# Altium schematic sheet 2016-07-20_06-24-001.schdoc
size 267 x 118 mm; SheetNumber: 1; SheetTotal: 1
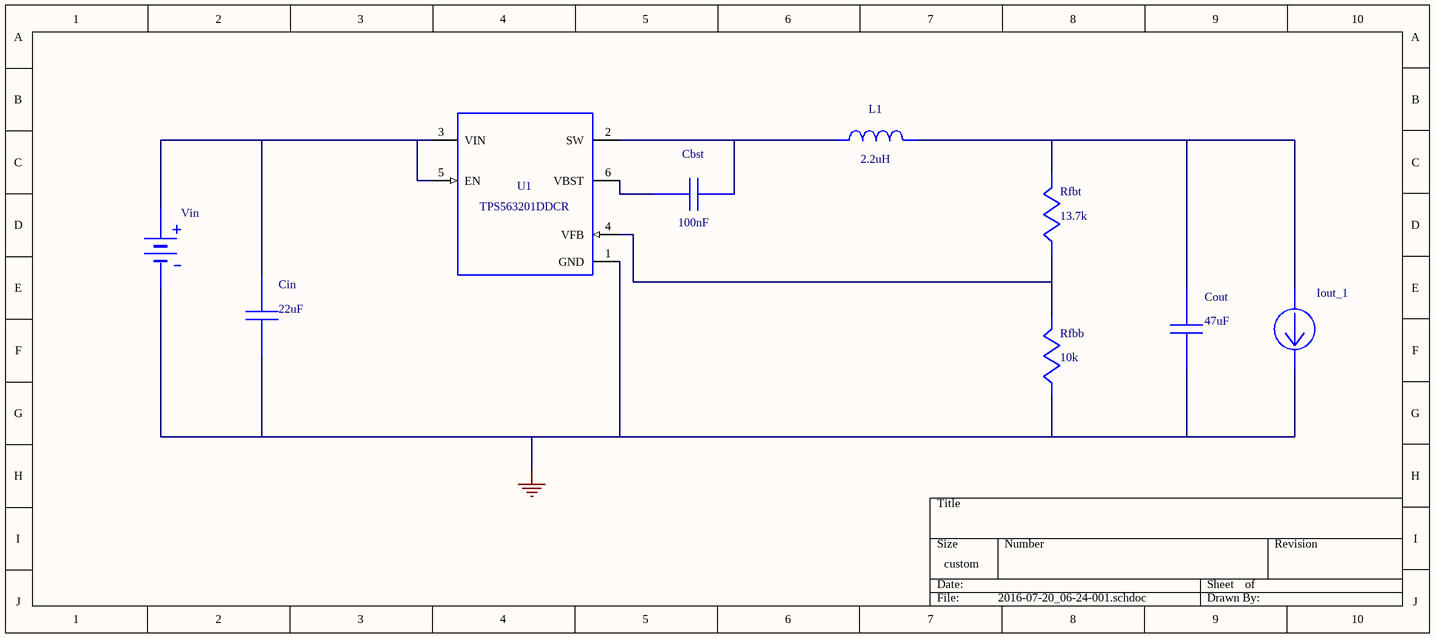
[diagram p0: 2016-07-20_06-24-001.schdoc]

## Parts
Cbst  value 100nF  (hidden comment: 08053C104KAT2A)
Cin  value 22uF  (hidden comment: GRM31CR61A226KE19L)
Cout  value 47uF  (hidden comment: C3216X5R1E476M160AC)
Iout_1  WB_CURRENT_LOAD  (value not drawn)
L1  value 2.2uH  (hidden comment: VLP8040T-2R2N)
Rfbb  value 10k  (hidden comment: CRCW040210K0FKED)
Rfbt  value 13.7k  (hidden comment: CRCW040213K7FKED)
U1  TPS563201DDCR
Vin  WB_BATTERY  (value not drawn)

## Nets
0: Cin.2 Cout.2 Iout_1.2(-) Rfbb.2 U1.1(GND) Vin.2(-)
NetCbst_1: Cbst.1 L1.1 U1.2(SW)
NetCbst_2: Cbst.2 U1.6(VBST)
NetCin_1: Cin.1 U1.3(VIN) U1.5(EN) Vin.1(+)
NetCout_1: Cout.1 Iout_1.1(+) L1.2 Rfbt.1
NetRfbb_1: Rfbb.1 Rfbt.2 U1.4(VFB)

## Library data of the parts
Cbst = 08053C104KAT2A: Manufacturer Name: AVX
Cin = GRM31CR61A226KE19L: GRM31CR61A226KE1; Manufacturer Name: MuRata
Cout = C3216X5R1E476M160AC: C3216X5R1E476M16; Manufacturer Name: TDK
L1 = VLP8040T-2R2N: Unknown; Manufacturer Name: TDK
Rfbb = CRCW040210K0FKED: Manufacturer Name: Vishay-Dale
Rfbt = CRCW040213K7FKED: Manufacturer Name: Vishay-Dale
U1 = TPS563201DDCR: Manufacturer Name: Texas Instruments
